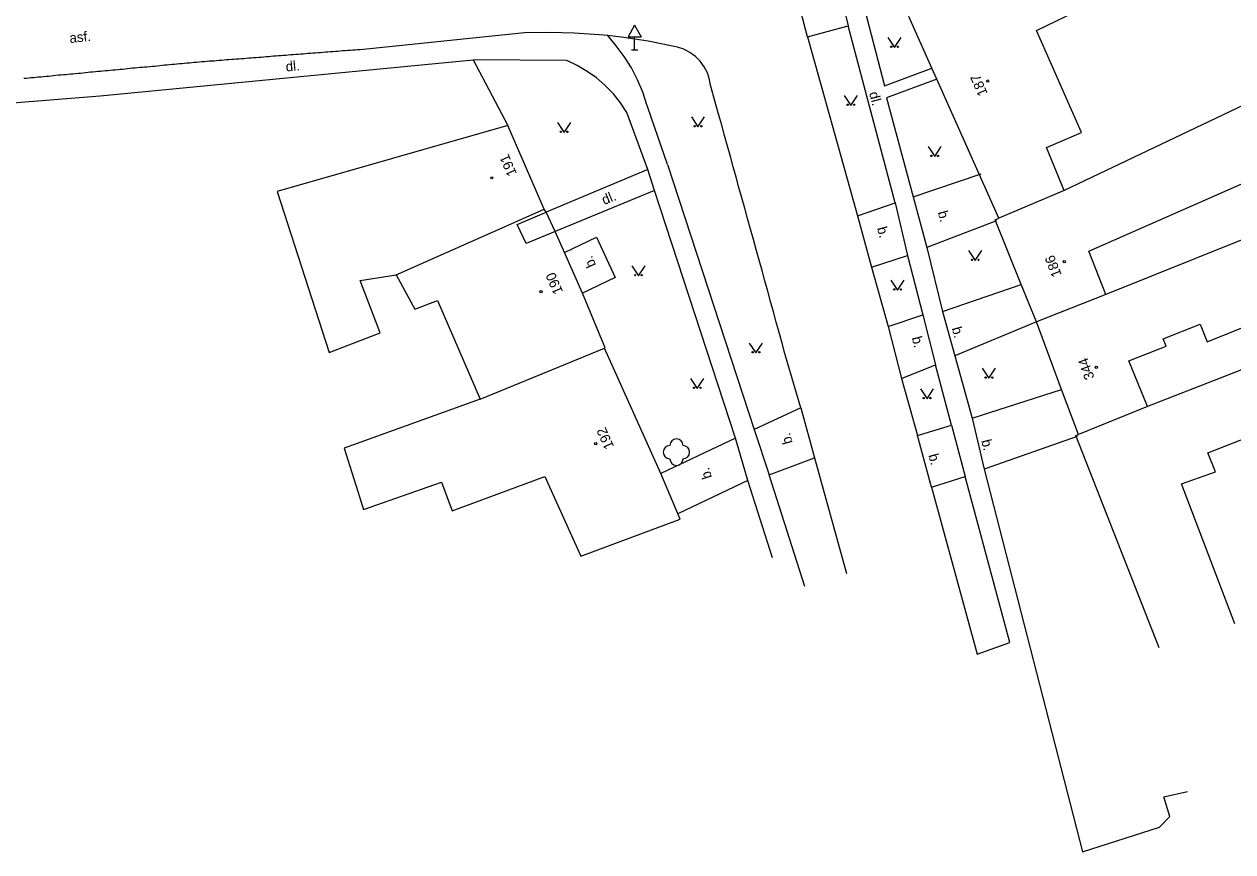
# Model space of a CAD drawing. Extents: x -545714 to -535419, y -1201788 to -1194297.
# Drawn here: x -535590.1 to -535498.7, y -1201665.1 to -1201602.5 of the extents above; entities that cross this region are included whole.
import ezdxf

# ---------------------------------------------------------------- set-up
doc = ezdxf.new("R2010")
doc.units = 0
for name, color, linetype in [('Vrstva 10', 7, 'Continuous'), ('Vrstva 11', 7, 'Continuous'), ('Vrstva 12', 7, 'Continuous'), ('Vrstva 15', 7, 'Continuous'), ('Vrstva 3', 7, 'Continuous'), ('Vrstva 4', 7, 'Continuous'), ('Vrstva 5', 7, 'Continuous'), ('Vrstva 8', 7, 'Continuous'), ('Vrstva 9', 7, 'Continuous')]:
    doc.layers.add(name, color=color, linetype=linetype)

msp = doc.modelspace()

# ---------------------------------------------------------------- linework, layer by layer
at = {"layer": 'Vrstva 10'}
for p, q in [((-535543.91, -1201602.614), (-535544.41, -1201603.48)), ((-535543.91, -1201602.614), (-535543.41, -1201603.48)), ((-535544.41, -1201603.48), (-535543.41, -1201603.48)), ((-535543.91, -1201604.48), (-535543.91, -1201603.48)), ((-535544.16, -1201604.48), (-535543.66, -1201604.48))]:
    msp.add_line(p, q, dxfattribs=at)
for points in [[(-535592.23, -1201608.58), (-535584.33, -1201607.95), (-535556.13, -1201605.24)], [(-535556.13, -1201605.24), (-535553.51, -1201610.19)]]:
    msp.add_lwpolyline(points, dxfattribs=at)
at = {"layer": 'Vrstva 11'}
for points in [[(-535530.74, -1201585.15), (-535525.02, -1201607.19), (-535521.43, -1201605.87)], [(-535528.76, -1201598.67), (-535527.76, -1201602.65)], [(-535530.83, -1201603.48), (-535531.87, -1201599.53)], [(-535530.83, -1201603.48), (-535527.76, -1201602.65)], [(-535524.22, -1201616.04), (-535527.76, -1201602.65)], [(-535545.95, -1201603.4), (-535546.6, -1201603.33), (-535548.48, -1201603.2), (-535550.35, -1201603.15), (-535552.23, -1201603.18), (-535564.67, -1201604.46), (-535564.86, -1201604.48), (-535565.04, -1201604.49), (-535565.23, -1201604.5), (-535565.42, -1201604.52), (-535565.61, -1201604.53), (-535565.79, -1201604.55), (-535565.98, -1201604.56), (-535566.17, -1201604.58), (-535566.36, -1201604.59), (-535566.54, -1201604.6), (-535566.73, -1201604.62), (-535566.92, -1201604.63), (-535567.1, -1201604.65), (-535567.29, -1201604.66), (-535567.48, -1201604.68), (-535567.67, -1201604.69), (-535567.85, -1201604.7), (-535568.04, -1201604.72), (-535568.23, -1201604.73), (-535568.41, -1201604.75), (-535568.6, -1201604.76), (-535568.79, -1201604.77), (-535568.98, -1201604.79), (-535569.16, -1201604.8), (-535569.35, -1201604.82), (-535569.54, -1201604.83), (-535569.72, -1201604.85), (-535569.91, -1201604.86), (-535570.1, -1201604.88), (-535570.29, -1201604.89), (-535570.47, -1201604.91), (-535570.66, -1201604.92), (-535570.85, -1201604.93), (-535571.03, -1201604.95), (-535571.22, -1201604.96), (-535571.41, -1201604.98), (-535571.59, -1201604.99), (-535571.78, -1201605.01), (-535571.97, -1201605.02), (-535572.16, -1201605.04), (-535572.34, -1201605.05), (-535572.53, -1201605.07), (-535572.72, -1201605.08), (-535572.9, -1201605.09), (-535573.09, -1201605.11), (-535573.28, -1201605.12), (-535573.47, -1201605.14), (-535573.65, -1201605.15), (-535573.84, -1201605.17), (-535574.03, -1201605.18), (-535574.21, -1201605.2), (-535574.4, -1201605.21), (-535574.59, -1201605.23), (-535574.78, -1201605.24), (-535574.96, -1201605.25), (-535575.15, -1201605.27), (-535575.34, -1201605.28), (-535575.52, -1201605.3), (-535575.71, -1201605.32), (-535575.9, -1201605.33), (-535576.09, -1201605.34), (-535576.27, -1201605.36), (-535576.46, -1201605.37), (-535576.65, -1201605.39), (-535576.83, -1201605.4), (-535577.02, -1201605.42), (-535577.21, -1201605.43), (-535577.4, -1201605.45), (-535577.58, -1201605.47), (-535577.77, -1201605.49), (-535577.95, -1201605.5), (-535578.14, -1201605.52), (-535578.33, -1201605.54), (-535578.52, -1201605.56), (-535578.7, -1201605.57), (-535578.89, -1201605.59), (-535579.08, -1201605.61), (-535579.26, -1201605.63), (-535579.45, -1201605.64), (-535579.64, -1201605.66), (-535579.82, -1201605.68), (-535580.01, -1201605.7), (-535580.2, -1201605.72), (-535580.38, -1201605.73), (-535580.57, -1201605.75), (-535580.76, -1201605.77), (-535580.94, -1201605.79), (-535581.13, -1201605.8), (-535581.32, -1201605.82), (-535581.51, -1201605.84), (-535581.69, -1201605.86), (-535581.88, -1201605.87), (-535582.07, -1201605.89), (-535582.25, -1201605.91), (-535582.44, -1201605.93)], [(-535533.41, -1201624.29), (-535533.63, -1201623.5), (-535533.85, -1201622.72), (-535534.07, -1201621.94), (-535534.28, -1201621.15), (-535534.5, -1201620.37), (-535534.72, -1201619.58), (-535534.93, -1201618.8), (-535535.15, -1201618.02), (-535535.37, -1201617.23), (-535535.59, -1201616.45), (-535535.8, -1201615.67), (-535536.02, -1201614.88), (-535536.24, -1201614.1), (-535536.45, -1201613.31), (-535536.67, -1201612.53), (-535536.89, -1201611.75), (-535537.11, -1201610.96), (-535537.32, -1201610.18), (-535537.54, -1201609.4), (-535537.76, -1201608.61), (-535538.19, -1201607.04), (-535538.25, -1201606.71), (-535538.41, -1201606.22), (-535538.65, -1201605.76), (-535538.95, -1201605.34), (-535539.31, -1201604.98), (-535539.73, -1201604.67), (-535540.18, -1201604.43), (-535540.67, -1201604.27), (-535541.04, -1201604.19), (-535542.88, -1201603.82), (-535544.74, -1201603.53), (-535545.95, -1201603.4)], [(-535541.42, -1201613.13), (-535542.92, -1201608.83), (-535542.98, -1201608.63), (-535543.3, -1201607.67), (-535543.69, -1201606.73), (-535544.16, -1201605.83), (-535544.69, -1201604.97), (-535545.3, -1201604.16), (-535545.95, -1201603.4)], [(-535530.83, -1201603.48), (-535527.05, -1201617.02)], [(-535542.91, -1201613.52), (-535544.5, -1201609.21), (-535544.98, -1201608.48), (-535545.52, -1201607.8), (-535546.13, -1201607.17), (-535546.79, -1201606.6), (-535547.5, -1201606.1), (-535548.25, -1201605.66), (-535549.04, -1201605.29), (-535556.13, -1201605.24)], [(-535582.44, -1201605.93), (-535582.63, -1201605.95), (-535582.81, -1201605.96), (-535583, -1201605.98), (-535583.19, -1201606), (-535583.37, -1201606.01), (-535583.56, -1201606.03), (-535583.75, -1201606.05), (-535583.93, -1201606.07), (-535584.12, -1201606.09), (-535584.31, -1201606.1), (-535584.5, -1201606.12), (-535584.68, -1201606.14), (-535584.87, -1201606.16), (-535585.06, -1201606.17), (-535585.24, -1201606.19), (-535585.43, -1201606.21), (-535585.62, -1201606.23), (-535585.8, -1201606.25), (-535585.99, -1201606.26), (-535586.18, -1201606.28), (-535586.36, -1201606.3), (-535586.55, -1201606.32), (-535586.74, -1201606.33), (-535586.92, -1201606.35), (-535587.11, -1201606.37), (-535587.3, -1201606.39), (-535587.48, -1201606.4), (-535587.67, -1201606.42), (-535587.86, -1201606.44), (-535588.04, -1201606.46), (-535588.23, -1201606.48), (-535588.42, -1201606.49), (-535588.61, -1201606.51), (-535588.79, -1201606.53), (-535588.98, -1201606.55), (-535589.17, -1201606.56), (-535589.35, -1201606.58), (-535589.54, -1201606.6), (-535589.73, -1201606.62), (-535589.91, -1201606.63), (-535590.1, -1201606.65)], [(-535521.06, -1201606.7), (-535524.87, -1201608.1), (-535522.85, -1201615.58), (-535517.7, -1201613.86)], [(-535542.91, -1201613.52), (-535550.61, -1201616.74)], [(-535542.41, -1201615.11), (-535542.91, -1201613.52)], [(-535541.42, -1201613.13), (-535534.86, -1201633.17)], [(-535542.41, -1201615.11), (-535549.91, -1201618.2)], [(-535536.29, -1201633.84), (-535542.41, -1201615.11)], [(-535522.85, -1201615.58), (-535521.82, -1201619.42)], [(-535527.05, -1201617.02), (-535524.22, -1201616.04)], [(-535524.22, -1201616.04), (-535523.27, -1201620.02)], [(-535527.05, -1201617.02), (-535525.99, -1201620.9)], [(-535516.55, -1201617.4), (-535521.82, -1201619.42)], [(-535549.21, -1201619.8), (-535546.79, -1201618.64), (-535545.39, -1201621.69), (-535547.86, -1201622.88)], [(-535525.99, -1201620.9), (-535523.27, -1201620.02)], [(-535523.27, -1201620.02), (-535522.12, -1201624.5)], [(-535521.82, -1201619.42), (-535520.62, -1201624.25), (-535514.68, -1201622.21)], [(-535525.99, -1201620.9), (-535524.75, -1201625.39)], [(-535531.34, -1201631.54), (-535532.33, -1201628.21), (-535532.55, -1201627.42), (-535532.76, -1201626.64), (-535532.98, -1201625.85), (-535533.2, -1201625.07), (-535533.41, -1201624.29)], [(-535524.75, -1201625.39), (-535522.12, -1201624.5)], [(-535522.12, -1201624.5), (-535521.16, -1201628.3)], [(-535520.62, -1201624.25), (-535519.71, -1201627.6)], [(-535524.75, -1201625.39), (-535523.74, -1201629.32)], [(-535513.53, -1201625.03), (-535519.71, -1201627.6), (-535518.4, -1201632.31), (-535511.63, -1201630.16)], [(-535523.74, -1201629.32), (-535521.16, -1201628.3)], [(-535522.53, -1201633.64), (-535519.95, -1201632.86), (-535521.16, -1201628.3)], [(-535523.74, -1201629.32), (-535522.53, -1201633.64)], [(-535531.34, -1201631.54), (-535534.86, -1201633.17)], [(-535531.34, -1201631.54), (-535530.32, -1201635.31)], [(-535519.95, -1201632.86), (-535518.91, -1201636.72)], [(-535518.4, -1201632.31), (-535517.48, -1201636.17)], [(-535536.29, -1201633.84), (-535541.93, -1201636.51)], [(-535535.34, -1201637.04), (-535536.29, -1201633.84)], [(-535534.86, -1201633.17), (-535533.73, -1201636.6)], [(-535521.47, -1201637.53), (-535522.53, -1201633.64)], [(-535510.45, -1201633.72), (-535517.48, -1201636.17), (-535510.05, -1201665.11), (-535504.22, -1201663.25), (-535503.45, -1201662.44), (-535503.89, -1201660.96), (-535502.11, -1201660.54)], [(-535533.73, -1201636.6), (-535530.32, -1201635.31)], [(-535530.32, -1201635.31), (-535527.9, -1201644.06)], [(-535531.05, -1201645.04), (-535533.73, -1201636.6)], [(-535535.34, -1201637.04), (-535540.59, -1201639.52)], [(-535533.49, -1201642.88), (-535535.34, -1201637.04)], [(-535521.47, -1201637.53), (-535518.91, -1201636.72)], [(-535521.47, -1201637.53), (-535518, -1201650.17)], [(-535518, -1201650.17), (-535515.54, -1201649.28), (-535518.91, -1201636.72)]]:
    msp.add_lwpolyline(points, dxfattribs=at)
at = {"layer": 'Vrstva 12'}
msp.add_circle((-535540.75, -1201634.89), 0.0005, dxfattribs=at)
for centre, start, end in [((-535541.25, -1201634.89), 89.99999, 269.99999), ((-535540.75, -1201634.39), 0, 179.99999), ((-535540.25, -1201634.89), 270, 89.99999), ((-535540.75, -1201635.39), 179.99999, 359.99999)]:
    msp.add_arc(centre, 0.5, start, end, dxfattribs=at)
at = {"layer": 'Vrstva 3'}
for points in [[(-535524.76, -1201603.54), (-535524.26, -1201604.29), (-535523.76, -1201603.54)], [(-535528.06, -1201607.92), (-535527.56, -1201608.67), (-535527.06, -1201607.92)], [(-535549.74, -1201609.96), (-535549.24, -1201610.71), (-535548.74, -1201609.96)], [(-535539.62, -1201609.55), (-535539.12, -1201610.3), (-535538.62, -1201609.55)], [(-535521.72, -1201611.79), (-535521.22, -1201612.54), (-535520.72, -1201611.79)], [(-535518.66, -1201619.65), (-535518.16, -1201620.4), (-535517.66, -1201619.65)], [(-535544.12, -1201620.81), (-535543.62, -1201621.56), (-535543.12, -1201620.81)], [(-535524.53, -1201621.89), (-535524.03, -1201622.64), (-535523.53, -1201621.89)], [(-535535.24, -1201626.64), (-535534.74, -1201627.39), (-535534.24, -1201626.64)], [(-535517.62, -1201628.55), (-535517.12, -1201629.3), (-535516.62, -1201628.55)], [(-535539.68, -1201629.32), (-535539.18, -1201630.07), (-535538.68, -1201629.32)], [(-535522.3, -1201630.1), (-535521.8, -1201630.85), (-535521.3, -1201630.1)]]:
    msp.add_lwpolyline(points, dxfattribs=at)
for centre in [(-535524.51, -1201604.24), (-535524.01, -1201604.24), (-535527.81, -1201608.62), (-535527.31, -1201608.62), (-535549.49, -1201610.66), (-535548.99, -1201610.66), (-535539.37, -1201610.25), (-535538.87, -1201610.25), (-535521.47, -1201612.49), (-535520.97, -1201612.49), (-535518.41, -1201620.35), (-535517.91, -1201620.35), (-535543.87, -1201621.51), (-535543.37, -1201621.51), (-535524.28, -1201622.59), (-535523.78, -1201622.59), (-535534.99, -1201627.34), (-535534.49, -1201627.34), (-535517.37, -1201629.25), (-535516.87, -1201629.25), (-535539.43, -1201630.02), (-535538.93, -1201630.02), (-535522.05, -1201630.8), (-535521.55, -1201630.8)]:
    msp.add_circle(centre, 0.05, dxfattribs=at)
at = {"layer": 'Vrstva 4'}
for points in [[(-535516.38, -1201617.2), (-535521.06, -1201606.7), (-535521.43, -1201605.87), (-535523.18, -1201601.94)], [(-535553.51, -1201610.19), (-535570.93, -1201615.18)], [(-535550.76, -1201616.51), (-535553.51, -1201610.19)], [(-535549.91, -1201618.2), (-535552.12, -1201619.12), (-535552.8, -1201617.68), (-535550.61, -1201616.74)], [(-535550.61, -1201616.74), (-535550.76, -1201616.51)], [(-535549.91, -1201618.2), (-535550.61, -1201616.74)], [(-535513.53, -1201625.03), (-535514.68, -1201622.21), (-535516.66, -1201617.32), (-535516.38, -1201617.2)], [(-535546.2, -1201627.04), (-535546.14, -1201627), (-535547.86, -1201622.88), (-535549.21, -1201619.8), (-535549.91, -1201618.2)], [(-535510.36, -1201633.56), (-535511.63, -1201630.16), (-535513.53, -1201625.03)], [(-535540.48, -1201639.96), (-535541.93, -1201636.51), (-535546.2, -1201627.04)], [(-535504.24, -1201649.68), (-535510.54, -1201633.63), (-535510.36, -1201633.56)]]:
    msp.add_lwpolyline(points, dxfattribs=at)
at = {"layer": 'Vrstva 5'}
for points in [[(-535511.42, -1201615.11), (-535512.76, -1201611.86), (-535510.13, -1201610.73), (-535513.53, -1201603.02), (-535501.82, -1201597.33), (-535501.47, -1201598.07), (-535500.97, -1201597.79), (-535502.17, -1201595.2), (-535503.72, -1201591.89), (-535522.9, -1201601.79)], [(-535508.29, -1201622.96), (-535509.57, -1201619.7), (-535497.15, -1201614.22), (-535497.36, -1201613.69), (-535491.66, -1201611.18), (-535493.68, -1201606.66), (-535511.42, -1201615.11), (-535516.38, -1201617.2)], [(-535505.12, -1201631.43), (-535506.53, -1201627.98), (-535503.73, -1201626.88), (-535503.95, -1201626.32), (-535501.16, -1201625.22), (-535500.63, -1201626.56), (-535492.18, -1201623.16), (-535492.7, -1201621.86), (-535491.84, -1201621.47), (-535492.19, -1201620.68), (-535480.05, -1201614.49), (-535476.82, -1201612.92), (-535479.05, -1201608.98), (-535482.17, -1201610.77), (-535494.6, -1201617.48), (-535508.29, -1201622.96), (-535513.53, -1201625.03)], [(-535570.93, -1201615.18), (-535567, -1201627.35), (-535563.15, -1201625.88), (-535564.66, -1201621.92), (-535561.95, -1201621.48), (-535550.76, -1201616.51)], [(-535561.95, -1201621.48), (-535560.53, -1201624.09), (-535558.82, -1201623.43), (-535555.6, -1201630.89), (-535546.2, -1201627.04)], [(-535498.53, -1201647.88), (-535502.55, -1201637.28), (-535499.99, -1201636.39), (-535500.56, -1201634.94), (-535486.94, -1201629.59), (-535488.98, -1201625.15), (-535505.12, -1201631.43), (-535510.36, -1201633.56)], [(-535555.6, -1201630.89), (-535565.88, -1201634.58), (-535564.42, -1201639.23), (-535558.52, -1201637.16), (-535557.71, -1201639.34), (-535550.71, -1201636.72), (-535547.98, -1201642.76), (-535540.48, -1201639.96)]]:
    msp.add_lwpolyline(points, dxfattribs=at)
at = {"layer": 'Vrstva 9'}
for centre in [(-535517.21, -1201606.84), (-535554.71, -1201614.15), (-535511.43, -1201620.49), (-535550.98, -1201622.76), (-535509, -1201628.48), (-535546.85, -1201634.26)]:
    msp.add_circle(centre, 0.0875, dxfattribs=at)

# ---------------------------------------------------------------- texts
at = {"layer": 'Vrstva 15'}
for s, rotation, p in [('asf.', 5.87001, (-535586.61, -1201603.96)), ('dl.', 5.49002, (-535570.26, -1201606.12)), ('dl.', 284.80999, (-535526.19, -1201607.74)), ('dl.', 22.38999, (-535546.21, -1201616.21)), ('b.', 285.01001, (-535521, -1201616.75)), ('b.', 285.27998, (-535525.59, -1201617.95)), ('b.', 114.66003, (-535546.81, -1201620.74)), ('b.', 285.2, (-535519.94, -1201625.52)), ('b.', 284.41, (-535522.96, -1201626.24)), ('b.', 105.13999, (-535531.96, -1201634.18)), ('b.', 283.41002, (-535517.7, -1201634.02)), ('b.', 285.23999, (-535521.7, -1201635.12)), ('b.', 107.70999, (-535538.05, -1201636.79))]:
    msp.add_text(s, height=0.75, rotation=rotation, dxfattribs=at).set_placement(p)
at = {"layer": 'Vrstva 8'}
for s, rotation, p in [('187', 113.56998, (-535517.2, -1201607.77)), ('191', 113.52001, (-535552.8, -1201613.83)), ('186', 111.51999, (-535511.61, -1201621.48)), ('190', 113.41997, (-535549.31, -1201622.76)), ('344', 109.67999, (-535509.13, -1201629.26)), ('192', 114.07, (-535545.45, -1201634.47))]:
    msp.add_text(s, height=0.75, rotation=rotation, dxfattribs=at).set_placement(p)

doc.saveas('drawing.dxf')
